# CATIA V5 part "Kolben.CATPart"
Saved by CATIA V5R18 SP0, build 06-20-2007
Part number: Kolben
Bounding box of the stored display mesh (mm): x -35.949 to 35.949, y -35.95 to 35.95, z 0 to 72.017
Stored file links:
  C:\Users\otto\Desktop\Rotax 600\CAD Modell\Kolben.CATPart
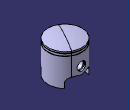
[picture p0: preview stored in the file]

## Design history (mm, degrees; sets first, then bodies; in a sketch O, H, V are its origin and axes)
Body1 (main body)
  Sketch1 on yz-plane, origin (0, 0, 0), H (0, 1, 0), V (0, 0, 1)
    line L1 (35.95, 0) -> (35.95, 59)
    point P1 (35.95, 0)
    line L2 (35.95, 59) -> (32.95, 59)
    line L3 (32.95, 59) -> (32.95, 60)
    line L4 (32.95, 60) -> (35.95, 60)
    point P5 (35.95, 60)
    line L5 (35.95, 60) -> (35.95, 64)
    line L6 (35.95, 64) -> (32.95, 64)
    point P7 (32.95, 64)
    line L7 (32.95, 64) -> (32.95, 65)
    line L8 (32.95, 65) -> (35.95, 65)
    point P9 (35.95, 65)
    line L9 (35.95, 65) -> (35.95, 68)
    point P10 (35.95, 68)
    point P11 (0, 72)
    line L10 (0, 72) -> (0, 0)
    line L11 (0, 0) -> (35.95, 0)
    spline S1 through (35.95, 68) (23.7825, 70.3997) (0, 72)
    point P12 (35.95, 68)
    point P13 (0, 72)
    distance L11 P12 = 68
    distance L10 L1 = 35.95
    length L10 = 72
    length L9 = 3
    length L7 = 1
    length L3 = 1
    distance L4 L6 = 4
    length L4 = 3
    coincidence: P1 H, P5 L1, P7 L3, P9 L1, P11 V, P12 P10, P13 P11
    vertical: L1 V, L3 V, L5 V, L7 V, L9 V, L10 V
    horizontal: L2 H, L4 H, L6 H, L8 H, L11 H
  Shaft1: profile Sketch1, axis Sketch1.L10, angle 360
  Sketch2 on zx-plane, origin (0, 0, 0), H (-1, 0, 0), V (0, 0, 1)
    circle A1 centre (0, 34) radius 9
    point P1 (0, 34)
    construction line L1 (0, 22.3093) -> (0, -22.7264)
    point P2 (0, 22.3093)
    radius A1 = 9
    distance P1 H = 34
    coincidence: P1 V, P2 V
  Pocket1: profile Sketch2, direction (0, -1, 0), through (limit type 3), opposite side through (limit type 3)
  Sketch3 on zx-plane, origin (0, 0, 0), H (-1, 0, 0), V (0, 0, 1)
    line L1 (6.6521, 20) -> (16, 20)
    arc A1 centre (16, 10) radius 10 from (16, 20) to (26, 10) cw
    line L2 (26, 10) -> (26, 0)
    point P1 (26, 0)
    line L3 (26, 0) -> (0, 0)
    point P2 (0, 18.5)
    point P3 (29, 0)
    point P4 (0, 0)
    point P5 (26, 10)
    point P6 (16, 20)
    point P7 (6.6521, 20)
    arc A2 centre (0, 34) radius 15.5 from (0, 18.5) to (6.6521, 20) ccw
    reference projected circle E1 centre (0, 34) radius 9 from edge [face of Shaft1 from Sketch1.L1 | face of Pocket1 from Sketch2.A1]
    point P10 (0, 0)
    point P11 (-26, 0)
    line L4 (-26, 0) -> (0, 0)
    point P12 (-26, 10)
    line L5 (-26, 10) -> (-26, 0)
    point P13 (-16, 20)
    arc A3 centre (-16, 10) radius 10 from (-16, 20) to (-26, 10) ccw
    point P15 (-6.6521, 20)
    line L6 (-6.6521, 20) -> (-16, 20)
    point P16 (0, 18.5)
    arc A4 centre (0, 34) radius 15.5 from (0, 18.5) to (-6.6521, 20) cw
    radius A2 = 15.5
    distance L1 L3 = 20
    radius A1 = 10
    length L2 = 10
    length L3 = 26
    tangency: A1 L1, L2 A1
    concentricity: E1 A2
    coincidence: P4 O, P2 V, P2 P16
    horizontal: L3 H
    symmetry: P4 P10 V, P1 P11 V, L3 L4 V, P5 P12 V, L2 L5 V, P6 P13 V, A1 A3 V, P7 P15 V, L1 L6 V, P2 P16 V, A2 A4 V
  Pocket2: profile Sketch3, direction (0, -1, 0), through (limit type 3), opposite side through (limit type 3)
  Sketch4 on xy-plane, origin (0, 0, 0), H (1, 0, 0), V (0, 1, 0)
    circle A1 centre (0, 0) radius 31
    radius A1 = 31
  Pocket3: profile Sketch4, direction (0, 0, 1), length 64
  Plane1: type Offset, RefPlane zx-plane, Offset 15
  Sketch5 on Plane1, origin (0, 15, 0), H (-1, 0, 0), V (0, 0, 1)
    point P1 (0, 33.9999)
    reference projected circle E1 centre (0, 34) radius 9 from edge [face of Pocket3 from Sketch4.A1 | face of Pocket1 from Sketch2.A1]
    projected circle E2 centre (0, 34) radius 9 from edge [face of Pocket3 from Sketch4.A1 | face of Pocket1 from Sketch2.A1]
    projected arc E3 centre (0, 33.9999) radius 15.4999 from (0, 18.5) to (6.6521, 20) ccw from edge [face of Pocket3 from Sketch4.A1 | face of Pocket2 from Sketch3.A2]
    arc A1 centre (0, 33.9999) radius 15.4999 from (6.6521, 20) to (0, 18.5) ccw
    concentricity: E1 P1
  Pad1: profile Sketch5, direction (0, 1, 0), up to the existing solid (limit type 2)
  Plane2: type Offset, RefPlane start face of Pad1, Offset -3, reversed
  Sketch6 on Plane2, origin (0, 18, 0), H (-1, 0, 0), V (0, 0, 1)
    projected arc E1 centre (0, 33.9999) radius 15.4999 from (6.6521, 20) to (0, 18.5) ccw from edge [start face of Pad1 | face of Pad1 from Sketch5.A1]
    projected arc E2 centre (0, 33.9999) radius 15.4999 from (12, 43.8106) to (10, 45.8426) ccw from edge [start face of Pad1 | face of Pad1 from Sketch5.A1]
    point P1 (6.6521, 20)
    point P2 (0, 18.5)
    line L1 (10, 64) -> (10, 45.8426)
    line L2 (12, 43.8106) -> (12, 64)
    point P3 (12, 43.8106)
    point P4 (10, 45.8426)
    point P5 (10, 64)
    point P6 (12, 64)
    point P7 (12, 64)
    point P8 (10, 64)
    point P9 (-12, 64)
    point P10 (-12, 43.8106)
    line L3 (-12, 43.8106) -> (-12, 64)
    point P11 (-10, 45.8426)
    point P12 (-10, 64)
    line L4 (-10, 64) -> (-10, 45.8426)
    point P13 (-10, 64)
    point P14 (-12, 64)
    point P15 (0, 18.5)
    point P16 (-6.6521, 20)
    line L5 (-12, 64) -> (-10, 64)
    construction arc A1 centre (0, 33.9999) radius 15.4999 from (-6.6521, 20) to (0, 18.5) cw
    arc A2 centre (0, 33.9999) radius 15.4999 from (-12, 43.8106) to (-10, 45.8426) cw
    line L6 (12, 64) -> (10, 64)
    distance L1 L2 = 2
    distance L1 V = 10
    vertical: L1 V, L2 V
    coincidence: E1 P4, L1 P5, L2 P6, P5 P8, P6 P7, P9 P14, P12 P13
    symmetry: P7 P9 V, P3 P10 V, L2 L3 V, P4 P11 V, P8 P12 V, L1 L4 V, P5 P13 V, P6 P14 V, P2 P15 V, P1 P16 V
    horizontal: L6 H
  Pad2: profile Sketch6, direction (0, 1, 0), up to the existing solid (limit type 2)
  Fillet1: radius 1, on start face of Pad2 (x2); start face of Pad1
  Mirror1: of Pad1, Pad2, Fillet1, about zx-plane
  Plane3: stored without definition
  Sketch7 on yz-plane, origin (0, 0, 0), H (0, 1, 0), V (0, 0, 1)
    construction line L1 (-31, 42.3462) -> (31, 42.3462)
    construction line L2 (31, 42.3462) -> (31, 25.7069)
    construction line L3 (31, 25.7069) -> (-31, 25.7069)
    construction line L4 (-31, 25.7069) -> (-31, 42.3462)
    circle A1 centre (32, 43) radius 1
    point P5 (32, 43)
    reference projected line E1 through (0, 34) direction (1, 0) from axis of face of Pocket1 from Sketch2.A1
    circle A2 centre (-32, 43) radius 1
    length L1 = 62
    radius A1 = 1
    distance P5 L2 = 1
    distance P5 E1 = 9
    horizontal: L1 H, L3 H
    vertical: L2 V, L4 V
    symmetry: L2 L4 V, A1 A2 V
  Groove1: profile Sketch7, axis axis of face of Pocket1 from Sketch2.A1, angle 360
  Plane4: stored without definition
